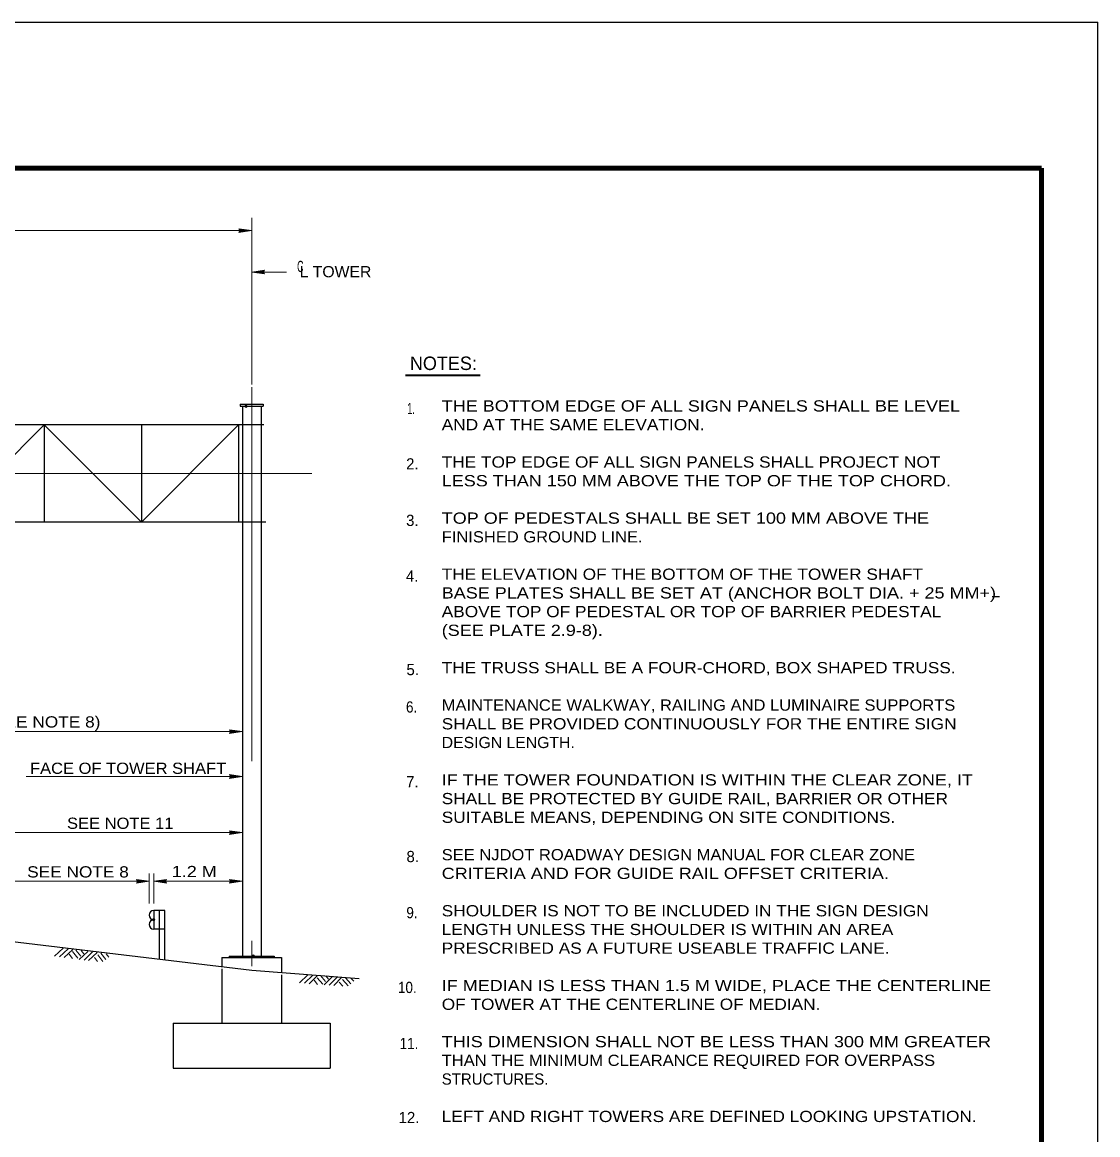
# Model space of a CAD drawing. Extents: x 312601.858 to 312602.699, y 144420.127 to 144420.721.
# Drawn here: x 312602.4113 to 312602.6988, y 144420.4233 to 144420.7208 of the extents above; entities that cross this region are included whole.
import ezdxf
from ezdxf.enums import TextEntityAlignment as Align

# ---------------------------------------------------------------- set-up
doc = ezdxf.new("R2010")
doc.units = 0
doc.header["$LTSCALE"] = 0.0012
doc.header["$PDMODE"] = 32
doc.header["$PDSIZE"] = 0.0006
doc.linetypes.add('DOT_DASHED', pattern=[7.7, 5, -1.2, 0.3, -1.2])
doc.linetypes.add('LONG_DASHED', pattern=[7.5, 6, -1.5])
for name, color, linetype, lineweight in [('1', 7, 'Continuous', 13), ('2', 7, 'Continuous', 13), ('39', 7, 'Continuous', 13)]:
    doc.layers.add(name, color=color, linetype=linetype, lineweight=lineweight)

msp = doc.modelspace()

# ---------------------------------------------------------------- hatches: boundary and pattern name
at = {"layer": '39'}
for points in [[(312602.4695, 144420.6651), (312602.4692, 144420.6656), (312602.4726, 144420.6651), (312602.4692, 144420.6646)], [(312602.4695, 144420.6651), (312602.4692, 144420.6656), (312602.4726, 144420.6651), (312602.4692, 144420.6646)], [(312602.4757, 144420.654), (312602.476, 144420.6535), (312602.4726, 144420.654), (312602.476, 144420.6545)], [(312602.467, 144420.5311), (312602.4667, 144420.5316), (312602.4701, 144420.5311), (312602.4667, 144420.5306)], [(312602.467, 144420.5311), (312602.4667, 144420.5316), (312602.4701, 144420.5311), (312602.4667, 144420.5306)], [(312602.467, 144420.5191), (312602.4667, 144420.5196), (312602.4701, 144420.5191), (312602.4667, 144420.5186)], [(312602.467, 144420.5041), (312602.4667, 144420.5046), (312602.4701, 144420.5041), (312602.4667, 144420.5036)], [(312602.4421, 144420.4911), (312602.4418, 144420.4916), (312602.4452, 144420.4911), (312602.4418, 144420.4906)], [(312602.4495, 144420.4911), (312602.4498, 144420.4906), (312602.4464, 144420.4911), (312602.4498, 144420.4916)], [(312602.467, 144420.4911), (312602.4667, 144420.4916), (312602.4701, 144420.4911), (312602.4667, 144420.4906)], [(312602.467, 144420.4911), (312602.4667, 144420.4916), (312602.4701, 144420.4911), (312602.4667, 144420.4906)]]:
    msp.add_hatch(color=256, dxfattribs=at).paths.add_polyline_path(points)

# ---------------------------------------------------------------- linework, layer by layer
at = {"layer": '1'}
for p, q in [((312602.4199, 144420.4711), (312602.4222, 144420.4732)), ((312602.4212, 144420.4709), (312602.4235, 144420.473)), ((312602.4225, 144420.4707), (312602.4248, 144420.4728)), ((312602.4238, 144420.4716), (312602.4247, 144420.4704)), ((312602.4247, 144420.4723), (312602.4261, 144420.4705)), ((312602.4256, 144420.4727), (312602.4269, 144420.4711)), ((312602.4265, 144420.4702), (312602.4288, 144420.4723)), ((312602.427, 144420.4726), (312602.4277, 144420.4717)), ((312602.4278, 144420.47), (312602.43, 144420.4722)), ((312602.429, 144420.4699), (312602.4313, 144420.472)), ((312602.4306, 144420.4707), (312602.4314, 144420.4696)), ((312602.4315, 144420.4714), (312602.4328, 144420.4696)), ((312602.4323, 144420.4719), (312602.4336, 144420.4702)), ((312602.4337, 144420.4717), (312602.4344, 144420.4708)), ((312602.4854, 144420.4639), (312602.4876, 144420.4661)), ((312602.4867, 144420.4638), (312602.4889, 144420.466)), ((312602.488, 144420.4637), (312602.4902, 144420.4659)), ((312602.4901, 144420.4653), (312602.4916, 144420.4636)), ((312602.491, 144420.4659), (312602.4923, 144420.4643)), ((312602.492, 144420.4634), (312602.4942, 144420.4656)), ((312602.4924, 144420.4658), (312602.4931, 144420.4649)), ((312602.4933, 144420.4633), (312602.4955, 144420.4655)), ((312602.4946, 144420.4632), (312602.4967, 144420.4654)), ((312602.4969, 144420.4648), (312602.4984, 144420.4631)), ((312602.4977, 144420.4653), (312602.4991, 144420.4637)), ((312602.4991, 144420.4652), (312602.4999, 144420.4644)), ((312602.4893, 144420.4646), (312602.4902, 144420.4635)), ((312602.496, 144420.4641), (312602.497, 144420.463))]:
    msp.add_line(p, q, dxfattribs=at)
at = {"layer": '2'}
msp.add_line((312602.4726, 144420.654), (312602.4819, 144420.654), dxfattribs=at)
at = {"layer": '39', "lineweight": 25}
for p, q in [((312601.8578, 144420.7208), (312602.6988, 144420.7208)), ((312602.6988, 144420.1268), (312602.6988, 144420.7208)), ((312602.5735, 144420.6818), (312602.6838, 144420.6818)), ((312602.6838, 144420.6687), (312602.6838, 144420.6818)), ((312602.4695, 144420.6187), (312602.4695, 144420.6181)), ((312602.4695, 144420.6181), (312602.4757, 144420.6181)), ((312602.4758, 144420.6131), (312601.9817, 144420.6131)), ((312602.3911, 144420.5871), (312602.4171, 144420.6131)), ((312602.4171, 144420.6131), (312602.4171, 144420.5871)), ((312602.4431, 144420.5871), (312602.4171, 144420.6131)), ((312602.4431, 144420.6131), (312602.4431, 144420.5871)), ((312602.4431, 144420.5871), (312602.4691, 144420.6131)), ((312602.4691, 144420.6131), (312602.4691, 144420.5871)), ((312602.4764, 144420.5871), (312601.9961, 144420.5871)), ((312602.6706, 144420.5672), (312602.6725, 144420.5672)), ((312602.4479, 144420.4833), (312602.4479, 144420.4704)), ((312602.4494, 144420.4702), (312602.4494, 144420.4833)), ((312602.4494, 144420.4783), (312602.4464, 144420.4783)), ((312602.4646, 144420.4707), (312602.4806, 144420.4707)), ((312602.4646, 144420.4707), (312602.4646, 144420.4682)), ((312602.4666, 144420.4711), (312602.4786, 144420.4711)), ((312602.4666, 144420.4711), (312602.4666, 144420.4707)), ((312602.4786, 144420.4711), (312602.4786, 144420.4707)), ((312602.4806, 144420.4707), (312602.4806, 144420.4667))]:
    msp.add_line(p, q, dxfattribs=at)
at = {"layer": '39', "lineweight": 158}
for p in [(312601.9088, 144420.6818), (312602.6838, 144420.142)]:
    msp.add_line(p, (312602.6838, 144420.6818), dxfattribs=at)
at = {"layer": '39'}
for p, q in [((312602.4726, 144420.6685), (312602.4726, 144420.6239)), ((312602.4726, 144420.6651), (312601.9456, 144420.6651)), ((312602.3103, 144420.5311), (312602.4701, 144420.5311)), ((312602.4123, 144420.5191), (312602.4701, 144420.5191)), ((312602.4071, 144420.5041), (312602.4701, 144420.5041)), ((312602.4452, 144420.4932), (312602.4452, 144420.4851)), ((312602.4464, 144420.4932), (312602.4464, 144420.4851)), ((312602.4071, 144420.4911), (312602.4452, 144420.4911)), ((312602.4096, 144420.4911), (312602.4229, 144420.4911)), ((312602.4464, 144420.4911), (312602.4582, 144420.4911)), ((312602.4556, 144420.4911), (312602.4701, 144420.4911)), ((312602.4726, 144420.4752), (312602.4726, 144420.4684))]:
    msp.add_line(p, q, dxfattribs=at)
at = {"layer": '39', "lineweight": 35}
msp.add_line((312602.5137, 144420.6264), (312602.5337, 144420.6264), dxfattribs=at)
at = {"layer": '39', "linetype": 'DOT_DASHED'}
for p, q in [((312602.4726, 144420.6232), (312602.4726, 144420.4752)), ((312602.003, 144420.6001), (312602.4887, 144420.6001))]:
    msp.add_line(p, q, dxfattribs=at)
at = {"layer": '39', "linetype": 'LONG_DASHED', "lineweight": 25}
for p, q in [((312602.4646, 144420.4677), (312602.4646, 144420.4531)), ((312602.4806, 144420.4661), (312602.4806, 144420.4531)), ((312602.4516, 144420.4531), (312602.4936, 144420.4531)), ((312602.4516, 144420.4531), (312602.4516, 144420.4411)), ((312602.4936, 144420.4531), (312602.4936, 144420.4411)), ((312602.4516, 144420.4411), (312602.4936, 144420.4411))]:
    msp.add_line(p, q, dxfattribs=at)
at = {"layer": '39'}
for points in [[(312602.4695, 144420.6651), (312602.4692, 144420.6656), (312602.4726, 144420.6651), (312602.4692, 144420.6646)], [(312602.4695, 144420.6651), (312602.4692, 144420.6656), (312602.4726, 144420.6651), (312602.4692, 144420.6646)], [(312602.4757, 144420.654), (312602.476, 144420.6535), (312602.4726, 144420.654), (312602.476, 144420.6545)], [(312602.467, 144420.5311), (312602.4667, 144420.5316), (312602.4701, 144420.5311), (312602.4667, 144420.5306)], [(312602.467, 144420.5311), (312602.4667, 144420.5316), (312602.4701, 144420.5311), (312602.4667, 144420.5306)], [(312602.467, 144420.5191), (312602.4667, 144420.5196), (312602.4701, 144420.5191), (312602.4667, 144420.5186)], [(312602.467, 144420.5041), (312602.4667, 144420.5046), (312602.4701, 144420.5041), (312602.4667, 144420.5036)], [(312602.4421, 144420.4911), (312602.4418, 144420.4916), (312602.4452, 144420.4911), (312602.4418, 144420.4906)], [(312602.4495, 144420.4911), (312602.4498, 144420.4906), (312602.4464, 144420.4911), (312602.4498, 144420.4916)], [(312602.467, 144420.4911), (312602.4667, 144420.4916), (312602.4701, 144420.4911), (312602.4667, 144420.4906)], [(312602.467, 144420.4911), (312602.4667, 144420.4916), (312602.4701, 144420.4911), (312602.4667, 144420.4906)]]:
    msp.add_lwpolyline(points, close=True, dxfattribs=at)
at = {"layer": '39', "lineweight": 25}
for points in [[(312602.4695, 144420.6187), (312602.4757, 144420.6187), (312602.4757, 144420.6181)], [(312602.4701, 144420.6181), (312602.4701, 144420.4746), (312602.4701, 144420.4711)], [(312602.4751, 144420.6181), (312602.4751, 144420.4745), (312602.4751, 144420.4711)], [(312602.4494, 144420.4833), (312602.4464, 144420.4833), (312602.4464, 144420.4783)], [(312602.4079, 144420.4751), (312602.4726, 144420.4673), (312602.5013, 144420.4651)]]:
    msp.add_lwpolyline(points, dxfattribs=at)
for centre in [(312602.4464, 144420.48205), (312602.4464, 144420.47955)]:
    msp.add_arc(centre, 0.00125, 90, 270, dxfattribs=at)
at = {"layer": '39'}
for p in [(312602.4711, 144420.6181), (312602.4464, 144420.4808), (312602.473, 144420.4711)]:
    msp.add_point(p, dxfattribs=at)

# ---------------------------------------------------------------- texts
at = {"layer": '2'}
for s, width, p in [('C', 0.6, (312602.4856, 144420.654)), ('L TOWER', 1.05, (312602.495, 144420.6526)), ('1.2 M', 1.2, (312602.45725, 144420.4922))]:
    msp.add_text(s, height=0.003, dxfattribs=dict(at, width=width)).set_placement(p, align=Align.CENTER)
at = {"layer": '39'}
for s, height, p in [('NOTES:', 0.0036, (312602.52385, 144420.6278)), ('2.', 0.003, (312602.51555, 144420.6012)), ('3.', 0.003, (312602.51555, 144420.5861)), ('4.', 0.003, (312602.5155, 144420.5712)), ('5.', 0.003, (312602.51565, 144420.5462)), ('7.', 0.003, (312602.51555, 144420.5162)), ('8.', 0.003, (312602.51565, 144420.4962)), ('12.', 0.003, (312602.51465, 144420.4264))]:
    msp.add_text(s, height=height, dxfattribs=at).set_placement(p, align=Align.CENTER)
for s, width, p in [('THE BOTTOM EDGE OF ALL SIGN PANELS SHALL BE LEVEL', 1.2, (312602.5234, 144420.6167)), ('AND AT THE SAME ELEVATION.', 1.15, (312602.5234, 144420.6117)), ('THE TOP EDGE OF ALL SIGN PANELS SHALL PROJECT NOT', 1.15, (312602.5234, 144420.6017)), ('LESS THAN 150 MM ABOVE THE TOP OF THE TOP CHORD.', 1.2, (312602.5234, 144420.5967)), ('TOP OF PEDESTALS SHALL BE SET 100 MM ABOVE THE', 1.2, (312602.5234, 144420.5867)), ('FINISHED GROUND LINE.', 1.1, (312602.5234, 144420.5817)), ('THE ELEVATION OF THE BOTTOM OF THE TOWER SHAFT', 1.15, (312602.5234, 144420.5717)), ('BASE PLATES SHALL BE SET AT (ANCHOR BOLT DIA. + 25 MM+)', 1.2, (312602.5234, 144420.5667)), ('ABOVE TOP OF PEDESTAL OR TOP OF BARRIER PEDESTAL', 1.15, (312602.5234, 144420.5617)), ('(SEE PLATE 2.9-8).', 1.2, (312602.5234, 144420.5567)), ('THE TRUSS SHALL BE A FOUR-CHORD, BOX SHAPED TRUSS.', 1.15, (312602.5234, 144420.5467)), ('MAINTENANCE WALKWAY, RAILING AND LUMINAIRE SUPPORTS', 1.1, (312602.5234, 144420.5367)), ('SHALL BE PROVIDED CONTINUOUSLY FOR THE ENTIRE SIGN', 1.15, (312602.5234, 144420.5317)), ('DESIGN LENGTH.', 1.05, (312602.5234, 144420.5267)), ('IF THE TOWER FOUNDATION IS WITHIN THE CLEAR ZONE, IT', 1.2, (312602.5234, 144420.5167)), ('SHALL BE PROTECTED BY GUIDE RAIL, BARRIER OR OTHER', 1.15, (312602.5234, 144420.5117)), ('SUITABLE MEANS, DEPENDING ON SITE CONDITIONS.', 1.15, (312602.5234, 144420.5067)), ('SEE NJDOT ROADWAY DESIGN MANUAL FOR CLEAR ZONE', 1.1, (312602.5234, 144420.4967)), ('CRITERIA AND FOR GUIDE RAIL OFFSET CRITERIA.', 1.2, (312602.5234, 144420.4917)), ('SHOULDER IS NOT TO BE INCLUDED IN THE SIGN DESIGN', 1.15, (312602.5234, 144420.4817)), ('LENGTH UNLESS THE SHOULDER IS WITHIN AN AREA', 1.15, (312602.5234, 144420.4767)), ('PRESCRIBED AS A FUTURE USEABLE TRAFFIC LANE.', 1.15, (312602.5234, 144420.4717)), ('IF MEDIAN IS LESS THAN 1.5 M WIDE, PLACE THE CENTERLINE', 1.2, (312602.5234, 144420.4617)), ('OF TOWER AT THE CENTERLINE OF MEDIAN.', 1.15, (312602.5234, 144420.4567)), ('THIS DIMENSION SHALL NOT BE LESS THAN 300 MM GREATER', 1.2, (312602.5234, 144420.4467)), ('THAN THE MINIMUM CLEARANCE REQUIRED FOR OVERPASS', 1.1, (312602.5234, 144420.4417)), ('LEFT AND RIGHT TOWERS ARE DEFINED LOOKING UPSTATION.', 1.15, (312602.5234, 144420.4267))]:
    msp.add_text(s, height=0.003, dxfattribs=dict(at, width=width)).set_placement(p)
for s, width, p in [('1.', 0.6, (312602.5152, 144420.616)), ('6.', 0.9, (312602.51535, 144420.5362)), ('DESIRABLE CLEAR ZONE (SEE NOTE 8) ', 1.15, (312602.3887, 144420.5322)), ('FACE OF TOWER SHAFT', 1.1, (312602.43955, 144420.5198)), ('SEE NOTE 11', 1.1, (312602.43745, 144420.5051)), ('SEE NOTE 8', 1.15, (312602.42615, 144420.4921)), ('9.', 0.9, (312602.51545, 144420.4812)), ('10.', 0.9, (312602.5142, 144420.4612)), ('11.', 0.9, (312602.51465, 144420.4462))]:
    msp.add_text(s, height=0.003, dxfattribs=dict(at, width=width)).set_placement(p, align=Align.CENTER)
msp.add_text('STRUCTURES.', height=0.003, dxfattribs=at).set_placement((312602.5234, 144420.4367))

doc.saveas('drawing.dxf')
